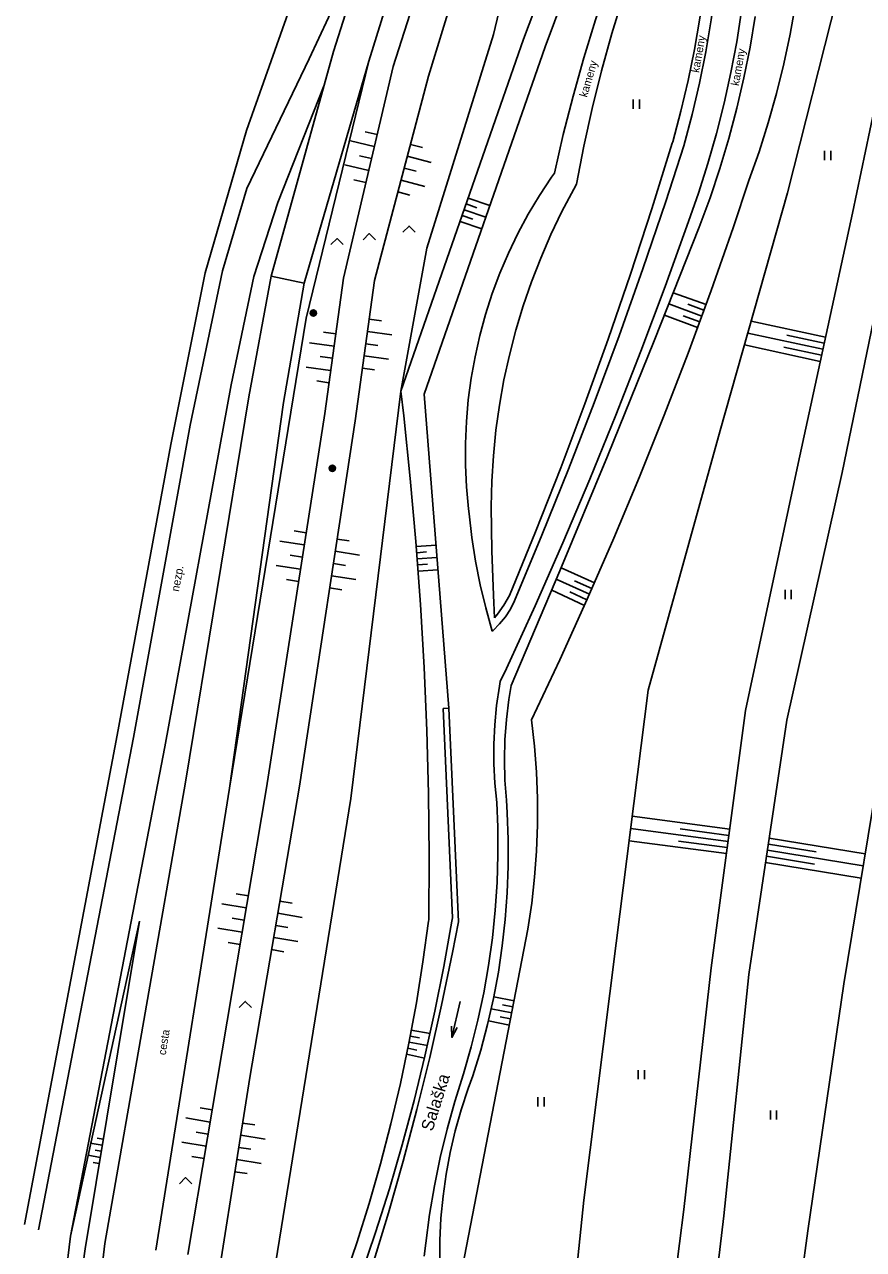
# Model space of a CAD drawing. Extents: x -539515 to -538098, y -1182060 to -1180157.
# Drawn here: x -539248.2 to -539180.1, y -1180855 to -1180755.5 of the extents above; entities that cross this region are included whole.
import ezdxf

# ---------------------------------------------------------------- set-up
doc = ezdxf.new("R2010")
doc.units = 0
for name, color, linetype in [('Vrstva 13', 7, 'Continuous'), ('Vrstva 23', 7, 'Continuous'), ('Vrstva 25', 7, 'Continuous'), ('Vrstva 27', 7, 'Continuous'), ('Vrstva 29', 7, 'Continuous'), ('Vrstva 36', 7, 'Continuous'), ('Vrstva 40', 7, 'Continuous'), ('Vrstva 45', 7, 'Continuous')]:
    doc.layers.add(name, color=color, linetype=linetype)

msp = doc.modelspace()

# ---------------------------------------------------------------- linework, layer by layer
at = {"layer": 'Vrstva 13'}
for p, q in [((-539220.29, -1180758.48), (-539211.35, -1180729.86)), ((-539225.12, -1180758.3), (-539219.507, -1180746.193)), ((-539189.344, -1180757.349), (-539188.929, -1180754.849)), ((-539230.17, -1180768.82), (-539225.12, -1180758.3)), ((-539225.53, -1180776.5), (-539220.29, -1180758.48)), ((-539223.902, -1180760.423), (-539227.65, -1180769.96)), ((-539197.313, -1180770.464), (-539195.653, -1180765.139)), ((-539195.653, -1180765.139), (-539195.62, -1180765.03)), ((-539232.15, -1180775.5), (-539230.17, -1180768.82)), ((-539227.65, -1180769.96), (-539229.6, -1180775.97)), ((-539199.049, -1180775.766), (-539197.313, -1180770.464)), ((-539197.12, -1180781.177), (-539193.47, -1180771.96)), ((-539234.78, -1180788.03), (-539232.15, -1180775.5)), ((-539229.6, -1180775.97), (-539231.46, -1180784.75)), ((-539230.03, -1180785.73), (-539228.21, -1180775.94)), ((-539228.21, -1180775.94), (-539225.53, -1180776.5)), ((-539200.861, -1180781.042), (-539199.049, -1180775.766)), ((-539227.21, -1180786.2), (-539225.53, -1180776.5)), ((-539207.752, -1180778.351), (-539207.079, -1180776.393)), ((-539202.749, -1180786.291), (-539200.861, -1180781.042)), ((-539200.913, -1180790.539), (-539197.12, -1180781.177)), ((-539231.46, -1180784.75), (-539236.82, -1180814.16)), ((-539235.16, -1180817.02), (-539230.03, -1180785.73)), ((-539231.58, -1180817.5), (-539227.21, -1180786.2)), ((-539204.711, -1180791.513), (-539202.749, -1180786.291)), ((-539239.37, -1180813.41), (-539234.78, -1180788.03)), ((-539204.78, -1180799.87), (-539200.913, -1180790.539)), ((-539206.748, -1180796.707), (-539204.711, -1180791.513)), ((-539208.86, -1180801.87), (-539206.748, -1180796.707)), ((-539208.72, -1180809.17), (-539204.78, -1180799.87)), ((-539214.25, -1180811.03), (-539213.785, -1180811.009)), ((-539213.49, -1180828.05), (-539214.25, -1180811.03)), ((-539247.095, -1180853.378), (-539239.37, -1180813.41)), ((-539236.82, -1180814.16), (-539244.5, -1180853.88)), ((-539241.69, -1180854.5), (-539235.16, -1180817.02)), ((-539237.57, -1180855.04), (-539231.58, -1180817.5)), ((-539208.966, -1180823.852), (-539208.965, -1180821.688)), ((-539215.722, -1180839.263), (-539214.915, -1180835.632)), ((-539212.219, -1180841.912), (-539211.83, -1180840.86)), ((-539218.61, -1180850.041), (-539217.57, -1180846.47)), ((-539244, -1180873.87), (-539241.69, -1180854.5))]:
    msp.add_line(p, q, dxfattribs=at)
for points in [[(-539219.507, -1180746.193), (-539223.14, -1180757.68)], [(-539201.39, -1180759.265), (-539200.557, -1180756.238), (-539199.648, -1180753.233), (-539198.663, -1180750.252)], [(-539193.848, -1180757.518), (-539193.413, -1180754.981), (-539193.058, -1180752.432), (-539192.782, -1180749.873)], [(-539223.14, -1180757.68), (-539223.902, -1180760.423)], [(-539195.62, -1180765.03), (-539194.951, -1180762.545), (-539194.36, -1180760.04), (-539193.848, -1180757.518)], [(-539191.061, -1180764.752), (-539190.411, -1180762.303), (-539189.838, -1180759.834), (-539189.344, -1180757.349)], [(-539203.42, -1180768.46), (-539202.821, -1180765.378), (-539202.144, -1180762.312), (-539201.39, -1180759.265)], [(-539223.902, -1180760.423), (-539228.21, -1180775.94)], [(-539193.47, -1180771.96), (-539192.591, -1180769.583), (-539191.788, -1180767.18), (-539191.061, -1180764.752)], [(-539207.079, -1180776.393), (-539206.33, -1180774.462), (-539205.507, -1180772.561), (-539204.612, -1180770.694), (-539203.645, -1180768.862), (-539203.42, -1180768.46)], [(-539209.677, -1180786.4), (-539209.313, -1180784.362), (-539208.87, -1180782.339), (-539208.35, -1180780.334), (-539207.752, -1180778.351)], [(-539210.34, -1180794.65), (-539210.294, -1180792.58), (-539210.168, -1180790.512), (-539209.962, -1180788.452), (-539209.677, -1180786.4)], [(-539210.34, -1180794.65), (-539210.293, -1180798.243), (-539210.166, -1180801.834), (-539210.07, -1180803.68)], [(-539208.86, -1180801.87), (-539209.314, -1180802.651), (-539209.835, -1180803.389), (-539210.07, -1180803.68)], [(-539209.11, -1180818.49), (-539209.23, -1180816.855), (-539209.269, -1180815.215), (-539209.229, -1180813.576), (-539209.109, -1180811.94), (-539208.909, -1180810.313), (-539208.72, -1180809.17)], [(-539208.965, -1180821.688), (-539209.044, -1180819.525), (-539209.11, -1180818.49)], [(-539209.768, -1180832.462), (-539209.448, -1180830.322), (-539209.208, -1180828.172), (-539209.047, -1180826.014), (-539208.966, -1180823.852)], [(-539214.915, -1180835.632), (-539214.186, -1180831.984), (-539213.535, -1180828.321), (-539213.49, -1180828.05)], [(-539211.83, -1180840.86), (-539211.198, -1180838.791), (-539210.644, -1180836.699), (-539210.167, -1180834.589), (-539209.768, -1180832.462)], [(-539217.57, -1180846.47), (-539216.607, -1180842.876), (-539215.722, -1180839.263)], [(-539214.253, -1180850.649), (-539214.003, -1180848.869), (-539213.673, -1180847.102), (-539213.266, -1180845.351), (-539212.781, -1180843.62), (-539212.219, -1180841.912)], [(-539220.919, -1180857.114), (-539219.727, -1180853.59), (-539218.61, -1180850.041)], [(-539214.31, -1180859.62), (-539214.458, -1180857.828), (-539214.527, -1180856.032), (-539214.516, -1180854.234), (-539214.424, -1180852.439), (-539214.253, -1180850.649)]]:
    msp.add_lwpolyline(points, dxfattribs=at)
at = {"layer": 'Vrstva 23'}
for p, q in [((-539216.06, -1180724.05), (-539230.21, -1180764.12)), ((-539230.21, -1180764.12), (-539233.56, -1180775.66)), ((-539233.56, -1180775.66), (-539236.34, -1180789.6)), ((-539236.34, -1180789.6), (-539240.71, -1180813.22)), ((-539240.71, -1180813.22), (-539248.22, -1180852.943))]:
    msp.add_line(p, q, dxfattribs=at)
at = {"layer": 'Vrstva 25'}
for centre, radius in [((-539224.78, -1180778.93), 0.25), ((-539224.78, -1180778.93), 0.2), ((-539224.78, -1180778.93), 0.15), ((-539224.78, -1180778.93), 0.1), ((-539224.78, -1180778.93), 0.05), ((-539223.24, -1180791.54), 0.25), ((-539223.24, -1180791.54), 0.2), ((-539223.24, -1180791.54), 0.15), ((-539223.24, -1180791.54), 0.1), ((-539223.24, -1180791.54), 0.05)]:
    msp.add_circle(centre, radius, dxfattribs=at)
at = {"layer": 'Vrstva 27'}
for p, q in [((-539219.833, -1180765.411), (-539221.78, -1180764.955)), ((-539219.604, -1180764.438), (-539220.578, -1180764.209)), ((-539220.061, -1180766.385), (-539221.035, -1180766.157)), ((-539216.904, -1180765.232), (-539215.936, -1180765.486)), ((-539220.289, -1180767.359), (-539222.237, -1180766.902)), ((-539217.412, -1180767.166), (-539216.445, -1180767.42)), ((-539217.158, -1180766.199), (-539215.224, -1180766.707)), ((-539220.518, -1180768.332), (-539221.491, -1180768.104)), ((-539217.666, -1180768.133), (-539215.732, -1180768.642)), ((-539217.92, -1180769.1), (-539216.953, -1180769.354)), ((-539212.382, -1180770.067), (-539211.502, -1180770.374)), ((-539212.217, -1180769.595), (-539210.457, -1180770.208)), ((-539212.711, -1180771.011), (-539211.831, -1180771.318)), ((-539212.546, -1180770.539), (-539210.786, -1180771.153)), ((-539212.875, -1180771.483), (-539211.115, -1180772.097)), ((-539192.916, -1180778.238), (-539195.572, -1180777.294)), ((-539193.602, -1180780.117), (-539196.294, -1180779.11)), ((-539193.257, -1180779.177), (-539195.924, -1180778.181)), ((-539193.086, -1180778.708), (-539194.402, -1180778.216)), ((-539220.249, -1180779.438), (-539219.259, -1180779.576)), ((-539193.429, -1180779.647), (-539194.762, -1180779.149)), ((-539183.222, -1180780.897), (-539189.254, -1180779.586)), ((-539222.965, -1180780.622), (-539223.956, -1180780.485)), ((-539220.388, -1180780.429), (-539218.407, -1180780.705)), ((-539183.434, -1180781.874), (-539189.527, -1180780.551)), ((-539183.328, -1180781.386), (-539186.359, -1180780.727)), ((-539223.102, -1180781.612), (-539225.083, -1180781.339)), ((-539220.526, -1180781.419), (-539219.536, -1180781.557)), ((-539183.647, -1180782.852), (-539189.799, -1180781.515)), ((-539183.541, -1180782.363), (-539186.602, -1180781.698)), ((-539223.239, -1180782.603), (-539224.23, -1180782.466)), ((-539220.664, -1180782.409), (-539218.683, -1180782.686)), ((-539223.376, -1180783.594), (-539225.357, -1180783.32)), ((-539220.803, -1180783.4), (-539219.812, -1180783.538)), ((-539223.513, -1180784.584), (-539224.503, -1180784.447)), ((-539225.361, -1180796.766), (-539226.349, -1180796.612)), ((-539225.515, -1180797.754), (-539227.491, -1180797.447)), ((-539222.858, -1180797.291), (-539221.869, -1180797.441)), ((-539216.432, -1180797.893), (-539214.826, -1180797.776)), ((-539225.668, -1180798.742), (-539226.656, -1180798.589)), ((-539223.008, -1180798.279), (-539221.031, -1180798.579)), ((-539216.395, -1180798.392), (-539215.591, -1180798.333)), ((-539216.359, -1180798.89), (-539214.748, -1180798.773)), ((-539225.821, -1180799.73), (-539227.798, -1180799.423)), ((-539223.158, -1180799.268), (-539222.169, -1180799.418)), ((-539216.323, -1180799.389), (-539215.516, -1180799.33)), ((-539216.286, -1180799.888), (-539214.669, -1180799.77)), ((-539201.971, -1180800.843), (-539204.678, -1180799.627)), ((-539225.975, -1180800.718), (-539226.963, -1180800.565)), ((-539223.308, -1180800.257), (-539221.331, -1180800.557)), ((-539202.374, -1180801.757), (-539205.065, -1180800.55)), ((-539202.172, -1180801.3), (-539203.587, -1180800.665)), ((-539223.458, -1180801.245), (-539222.469, -1180801.395)), ((-539202.782, -1180802.674), (-539205.435, -1180801.431)), ((-539202.578, -1180802.217), (-539203.98, -1180801.56)), ((-539190.997, -1180820.849), (-539198.9, -1180819.794)), ((-539191.13, -1180821.84), (-539199.026, -1180820.786)), ((-539191.064, -1180821.344), (-539195.013, -1180820.817)), ((-539191.262, -1180822.831), (-539199.152, -1180821.778)), ((-539191.196, -1180822.335), (-539195.143, -1180821.809)), ((-539180.004, -1180822.836), (-539187.783, -1180821.56)), ((-539180.166, -1180823.823), (-539187.93, -1180822.548)), ((-539183.971, -1180822.692), (-539187.857, -1180822.054)), ((-539180.328, -1180824.81), (-539188.077, -1180823.538)), ((-539184.125, -1180823.68), (-539188.003, -1180823.044)), ((-539230.057, -1180826.257), (-539231.043, -1180826.091)), ((-539227.494, -1180826.682), (-539226.508, -1180826.851)), ((-539230.223, -1180827.243), (-539232.195, -1180826.911)), ((-539227.662, -1180827.668), (-539225.69, -1180828.005)), ((-539230.389, -1180828.229), (-539231.375, -1180828.063)), ((-539227.83, -1180828.654), (-539226.844, -1180828.822)), ((-539230.555, -1180829.215), (-539232.527, -1180828.883)), ((-539227.998, -1180829.64), (-539226.027, -1180829.976)), ((-539230.721, -1180830.201), (-539231.707, -1180830.035)), ((-539228.166, -1180830.626), (-539227.181, -1180830.794)), ((-539208.494, -1180834.783), (-539210.141, -1180834.462)), ((-539208.683, -1180835.765), (-539210.349, -1180835.44)), ((-539208.589, -1180835.274), (-539209.421, -1180835.112)), ((-539208.873, -1180836.747), (-539210.575, -1180836.415)), ((-539208.778, -1180836.257), (-539209.626, -1180836.091)), ((-539216.925, -1180837.654), (-539216.171, -1180837.794)), ((-539216.833, -1180837.163), (-539215.308, -1180837.446)), ((-539217.117, -1180838.635), (-539216.382, -1180838.79)), ((-539217.016, -1180838.146), (-539215.528, -1180838.422)), ((-539217.22, -1180839.125), (-539215.762, -1180839.431)), ((-539232.984, -1180843.639), (-539233.97, -1180843.473)), ((-539233.15, -1180844.625), (-539235.122, -1180844.293)), ((-539230.522, -1180844.707), (-539229.534, -1180844.863)), ((-539233.316, -1180845.611), (-539234.302, -1180845.445)), ((-539230.678, -1180845.695), (-539228.703, -1180846.007)), ((-539241.911, -1180846.505), (-539242.897, -1180846.341)), ((-539241.829, -1180846.012), (-539242.322, -1180845.929)), ((-539233.482, -1180846.597), (-539235.454, -1180846.265)), ((-539230.834, -1180846.683), (-539229.846, -1180846.839)), ((-539242.075, -1180847.491), (-539243.062, -1180847.327)), ((-539241.993, -1180846.998), (-539242.486, -1180846.916)), ((-539233.648, -1180847.583), (-539234.634, -1180847.417)), ((-539230.99, -1180847.671), (-539229.014, -1180847.983)), ((-539242.157, -1180847.984), (-539242.65, -1180847.902)), ((-539231.146, -1180848.659), (-539230.158, -1180848.814))]:
    msp.add_line(p, q, dxfattribs=at)
at = {"layer": 'Vrstva 29'}
for p, q in [((-539218.31, -1180758.92), (-539209.11, -1180730.15)), ((-539206.48, -1180730.46), (-539215.45, -1180759.7)), ((-539207.72, -1180756.69), (-539201.32, -1180739.48)), ((-539205.966, -1180757.322), (-539199.573, -1180740.13)), ((-539207.52, -1180745.28), (-539210.17, -1180756.3)), ((-539181.35, -1180749.54), (-539186.31, -1180769.16)), ((-539176.92, -1180751.13), (-539181.03, -1180770.81)), ((-539217.68, -1180785.27), (-539207.72, -1180756.69)), ((-539210.17, -1180756.3), (-539215.56, -1180773.65)), ((-539190.426, -1180756.897), (-539190.892, -1180759.395)), ((-539215.791, -1180785.514), (-539205.966, -1180757.322)), ((-539220.29, -1180758.48), (-539225.36, -1180779.34)), ((-539222.34, -1180776.1), (-539218.31, -1180758.92)), ((-539215.45, -1180759.7), (-539219.81, -1180776.29)), ((-539196.182, -1180769.863), (-539194.71, -1180765.34)), ((-539190.723, -1180772.011), (-539189.43, -1180768.16)), ((-539186.31, -1180769.16), (-539191.76, -1180788.46)), ((-539198.041, -1180775.338), (-539196.182, -1180769.863)), ((-539181.03, -1180770.81), (-539185.45, -1180791.15)), ((-539194.35, -1180771.5), (-539196.237, -1180776.773)), ((-539192.508, -1180777.108), (-539190.723, -1180772.011)), ((-539177.74, -1180771.78), (-539181.88, -1180791.89)), ((-539215.56, -1180773.65), (-539217.68, -1180785.27)), ((-539223.86, -1180787.1), (-539222.34, -1180776.1)), ((-539210.259, -1180777.35), (-539209.638, -1180775.69)), ((-539199.975, -1180780.787), (-539198.041, -1180775.338)), ((-539219.81, -1180776.29), (-539221.4, -1180787.68)), ((-539196.237, -1180776.773), (-539198.199, -1180782.018)), ((-539194.369, -1180782.178), (-539192.508, -1180777.108)), ((-539225.36, -1180779.34), (-539231.58, -1180817.5)), ((-539201.984, -1180786.209), (-539199.975, -1180780.787)), ((-539198.199, -1180782.018), (-539200.235, -1180787.234)), ((-539196.304, -1180787.22), (-539194.369, -1180782.178)), ((-539217.68, -1180785.27), (-539221.73, -1180818.36)), ((-539217.448, -1180787.277), (-539217.68, -1180785.27)), ((-539213.785, -1180811.009), (-539215.791, -1180785.514)), ((-539204.069, -1180791.602), (-539201.984, -1180786.209)), ((-539228.58, -1180817.49), (-539223.86, -1180787.1)), ((-539221.4, -1180787.68), (-539225.9, -1180817.34)), ((-539216.915, -1180792.374), (-539217.448, -1180787.277)), ((-539200.235, -1180787.234), (-539202.346, -1180792.421)), ((-539198.314, -1180792.233), (-539196.304, -1180787.22)), ((-539191.76, -1180788.46), (-539197.6, -1180809.55)), ((-539206.227, -1180796.966), (-539204.069, -1180791.602)), ((-539185.45, -1180791.15), (-539189.71, -1180811.2)), ((-539181.88, -1180791.89), (-539186.36, -1180811.99)), ((-539216.462, -1180797.479), (-539216.915, -1180792.374)), ((-539202.346, -1180792.421), (-539204.531, -1180797.578)), ((-539200.398, -1180797.216), (-539198.314, -1180792.233)), ((-539212.143, -1180795.237), (-539212.18, -1180794.82)), ((-539208.46, -1180802.3), (-539206.227, -1180796.966)), ((-539216.089, -1180802.59), (-539216.462, -1180797.479)), ((-539204.531, -1180797.578), (-539206.789, -1180802.702)), ((-539202.556, -1180802.167), (-539200.398, -1180797.216)), ((-539215.795, -1180807.707), (-539216.089, -1180802.59)), ((-539206.789, -1180802.702), (-539209.12, -1180807.794)), ((-539204.787, -1180807.085), (-539202.556, -1180802.167)), ((-539215.581, -1180812.827), (-539215.795, -1180807.707)), ((-539209.12, -1180807.794), (-539209.61, -1180808.84)), ((-539207.09, -1180811.97), (-539204.787, -1180807.085)), ((-539197.6, -1180809.55), (-539200.21, -1180830.11)), ((-539213.01, -1180828.38), (-539213.785, -1180811.009)), ((-539189.71, -1180811.2), (-539192.5, -1180832.11)), ((-539215.448, -1180817.95), (-539215.581, -1180812.827)), ((-539186.36, -1180811.99), (-539189.43, -1180832.64)), ((-539178.47, -1180813.49), (-539181.74, -1180833.41)), ((-539234.96, -1180855.37), (-539228.58, -1180817.49)), ((-539225.9, -1180817.34), (-539229.94, -1180841.02)), ((-539221.73, -1180818.36), (-539227.98, -1180856.98)), ((-539215.394, -1180823.075), (-539215.448, -1180817.95)), ((-539215.42, -1180828.2), (-539215.394, -1180823.075)), ((-539238.88, -1180828.3), (-539244.5, -1180853.88)), ((-539243.31, -1180854.91), (-539238.88, -1180828.3)), ((-539207.37, -1180828.97), (-539212.67, -1180856.39)), ((-539200.21, -1180830.11), (-539202.82, -1180850.96)), ((-539192.5, -1180832.11), (-539194.73, -1180851.72)), ((-539189.43, -1180832.64), (-539191.48, -1180852.25)), ((-539181.74, -1180833.41), (-539184.66, -1180853.46)), ((-539217.721, -1180841.505), (-539217.031, -1180838.226)), ((-539229.94, -1180841.02), (-539232.26, -1180855.72)), ((-539217.498, -1180847.814), (-539216.379, -1180843.606)), ((-539220.258, -1180851.231), (-539219.335, -1180848.01)), ((-539202.82, -1180850.96), (-539204.95, -1180870.98)), ((-539194.73, -1180851.72), (-539197.32, -1180872.09)), ((-539191.48, -1180852.25), (-539193.9, -1180872.55)), ((-539184.66, -1180853.46), (-539187.45, -1180873.84)), ((-539244.5, -1180853.88), (-539246.9, -1180873.8)), ((-539245.9, -1180873.99), (-539243.31, -1180854.91))]:
    msp.add_line(p, q, dxfattribs=at)
for points in [[(-539202.827, -1180758.204), (-539201.875, -1180755.125), (-539200.847, -1180752.07), (-539199.744, -1180749.042)], [(-539186.609, -1180758.703), (-539186.097, -1180756.288), (-539185.664, -1180753.857), (-539185.309, -1180751.414), (-539185.034, -1180748.96)], [(-539192.928, -1180757.708), (-539192.49, -1180755.131), (-539192.132, -1180752.543), (-539191.853, -1180749.944)], [(-539189.503, -1180749.332), (-539189.731, -1180751.863), (-539190.039, -1180754.385), (-539190.426, -1180756.897)], [(-539205.22, -1180767.57), (-539204.5, -1180764.428), (-539203.702, -1180761.306), (-539202.827, -1180758.204)], [(-539194.71, -1180765.34), (-539194.038, -1180762.814), (-539193.444, -1180760.27), (-539192.928, -1180757.708)], [(-539189.43, -1180768.16), (-539188.61, -1180765.831), (-539187.866, -1180763.477), (-539187.199, -1180761.1), (-539186.609, -1180758.703)], [(-539190.892, -1180759.395), (-539191.437, -1180761.877), (-539192.059, -1180764.341), (-539192.759, -1180766.784)], [(-539192.759, -1180766.784), (-539193.535, -1180769.204), (-539194.35, -1180771.5)], [(-539209.638, -1180775.69), (-539208.943, -1180774.06), (-539208.175, -1180772.462), (-539207.336, -1180770.901), (-539206.428, -1180769.379), (-539205.451, -1180767.9), (-539205.22, -1180767.57)], [(-539212.209, -1180785.976), (-539211.976, -1180784.219), (-539211.663, -1180782.475), (-539211.272, -1180780.746), (-539210.804, -1180779.037), (-539210.259, -1180777.35)], [(-539212.18, -1180794.82), (-539212.346, -1180793.055), (-539212.431, -1180791.285), (-539212.437, -1180789.513), (-539212.363, -1180787.742), (-539212.209, -1180785.976)], [(-539210.26, -1180804.75), (-539210.793, -1180802.882), (-539211.248, -1180800.993), (-539211.625, -1180799.087), (-539211.924, -1180797.168), (-539212.143, -1180795.237)], [(-539208.46, -1180802.3), (-539208.796, -1180802.966), (-539209.201, -1180803.592), (-539209.671, -1180804.172), (-539210.2, -1180804.697), (-539210.26, -1180804.75)], [(-539209.88, -1180818.68), (-539210.046, -1180817.106), (-539210.132, -1180815.526), (-539210.139, -1180813.943), (-539210.065, -1180812.362), (-539209.912, -1180810.787), (-539209.679, -1180809.222), (-539209.61, -1180808.84)], [(-539207.09, -1180811.97), (-539206.846, -1180814.09), (-539206.681, -1180816.217), (-539206.596, -1180818.349), (-539206.592, -1180820.483)], [(-539209.798, -1180822.925), (-539209.806, -1180820.669), (-539209.88, -1180818.68)], [(-539206.592, -1180820.483), (-539206.667, -1180822.615), (-539206.822, -1180824.743), (-539207.057, -1180826.864), (-539207.37, -1180828.97)], [(-539210.563, -1180831.912), (-539210.252, -1180829.677), (-539210.021, -1180827.432), (-539209.869, -1180825.181), (-539209.798, -1180822.925)], [(-539215.886, -1180831.622), (-539215.433, -1180828.302), (-539215.42, -1180828.2)], [(-539214.374, -1180835.132), (-539213.489, -1180830.869), (-539213.01, -1180828.38)], [(-539217.031, -1180838.226), (-539216.419, -1180834.931), (-539215.886, -1180831.622)], [(-539212.59, -1180840.7), (-539211.967, -1180838.531), (-539211.421, -1180836.342), (-539210.952, -1180834.134), (-539210.563, -1180831.912)], [(-539216.379, -1180843.606), (-539215.338, -1180839.379), (-539214.374, -1180835.132)], [(-539212.59, -1180840.7), (-539213.296, -1180842.944), (-539213.926, -1180845.21), (-539214.477, -1180847.497), (-539214.951, -1180849.801)], [(-539219.335, -1180848.01), (-539218.489, -1180844.767), (-539217.721, -1180841.505)], [(-539219.966, -1180856.165), (-539218.694, -1180852.001), (-539217.498, -1180847.814)], [(-539214.951, -1180849.801), (-539215.347, -1180852.12), (-539215.663, -1180854.451), (-539215.78, -1180855.51)], [(-539222.333, -1180857.604), (-539221.257, -1180854.43), (-539220.258, -1180851.231)]]:
    msp.add_lwpolyline(points, dxfattribs=at)
at = {"layer": 'Vrstva 36'}
for p, q in [((-539198.82, -1180762.346), (-539198.82, -1180761.596)), ((-539198.32, -1180762.346), (-539198.32, -1180761.596)), ((-539183.297, -1180766.505), (-539183.297, -1180765.755)), ((-539182.797, -1180766.505), (-539182.797, -1180765.755)), ((-539186.501, -1180802.152), (-539186.501, -1180801.402)), ((-539186.001, -1180802.152), (-539186.001, -1180801.402)), ((-539198.414, -1180841.15), (-539198.414, -1180840.4)), ((-539197.914, -1180841.15), (-539197.914, -1180840.4)), ((-539206.563, -1180843.356), (-539206.563, -1180842.606)), ((-539206.063, -1180843.356), (-539206.063, -1180842.606)), ((-539187.695, -1180844.424), (-539187.695, -1180843.674)), ((-539187.195, -1180844.424), (-539187.195, -1180843.674))]:
    msp.add_line(p, q, dxfattribs=at)
for points in [[(-539217.517, -1180772.37), (-539217.017, -1180771.87), (-539216.517, -1180772.37)], [(-539223.357, -1180773.377), (-539222.857, -1180772.877), (-539222.357, -1180773.377)], [(-539220.739, -1180772.974), (-539220.239, -1180772.474), (-539219.739, -1180772.974)], [(-539230.809, -1180835.33), (-539230.309, -1180834.83), (-539229.809, -1180835.33)], [(-539235.643, -1180849.634), (-539235.143, -1180849.134), (-539234.643, -1180849.634)]]:
    msp.add_lwpolyline(points, dxfattribs=at)
at = {"layer": 'Vrstva 45'}
msp.add_line((-539212.863, -1180834.83), (-539213.531, -1180837.755), dxfattribs=at)
msp.add_lwpolyline([(-539213.112, -1180836.952), (-539213.531, -1180837.755), (-539213.56, -1180836.85)], dxfattribs=at)

# ---------------------------------------------------------------- texts
at = {"layer": 'Vrstva 40'}
for s, rotation, p in [('kameny', 79.9179, (-539193.484, -1180759.451)), ('kameny', 79.85753, (-539190.258, -1180760.514)), ('kameny', 73.78098, (-539202.577, -1180761.456)), ('nezp.', 79.67115, (-539235.691, -1180801.586)), ('cesta', 80.93413, (-539236.764, -1180839.22))]:
    msp.add_text(s, height=0.65, rotation=rotation, dxfattribs=at).set_placement(p)
at = {"layer": 'Vrstva 45'}
msp.add_text('Salaška', height=1, rotation=72.53555, dxfattribs=at).set_placement((-539215.119, -1180845.433))

doc.saveas('drawing.dxf')
